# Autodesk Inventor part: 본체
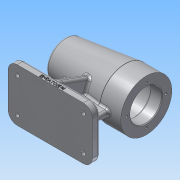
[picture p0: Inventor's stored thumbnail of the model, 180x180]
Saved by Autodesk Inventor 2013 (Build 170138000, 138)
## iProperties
Created: 2018-09
Part Number: 본체
Material: 알루미늄 6061
Document SubType Name: Modeling
Designer: Administrator
Density: 2.71 g/cm^3
Mass: 734.945 g
Surface Area: 663.118 cm^2
Volume: 271.197 cm^3
Author: Administrator
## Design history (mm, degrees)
sketch "스케치1"
  geometry: L1 (53.787, 34)-(25.787, 34); L2 (25.787, 34)-(-54.483, 24.144); L3 (53.787, 0)-(-58.213, 0); L4 (53.787, 34)-(53.787, 21); L5 (53.787, 21)-(38.787, 21); L6 (38.787, 21)-(38.787, 24); L7 (38.787, 24)-(-15.213, 24); L8 (-15.213, 24)-(-15.213, 21); L9 (-15.213, 21)-(-27.213, 21); L10 (-27.213, 21)-(-27.213, 17.5); L11 (-27.213, 17.5)-(-45.213, 17.5); L12 (-45.213, 17.5)-(-45.213, 16); L13 (-45.213, 16)-(-49.213, 16); L14 (-49.213, 16)-(-49.213, 10.5); L15 (-49.213, 10.5)-(-52.213, 10.5); L16 (-52.213, 10.5)-(-52.213, 0); A1 r 80 centre (21.787, 0) between (-54.483, 24.144) and (-58.213, 0); 3 further points
  constraints: 32 end point, 9 parallel, 5 perpendicular, 3 point on line, 2 point on circle, 1 centre point, 1 coincident, 1 horizontal, 1 horizontal alignment, 1 midpoint, 1 vertical alignment
  dimensions: "d1" = 68 diameter of L1 L3; "d3" = 7 deg angle of L2 L1; "d4" = 28 distance of L1.start L1.end; "d5" = 42 diameter of L5 L3; "d6" = 48 diameter of L7 L3; "d7" = 42 diameter of L9 L3; "d8" = 35 diameter of L11 L3; "d9" = 32 diameter of L13 L3; "d10" = 21 diameter of L15 L3; "d11" = 15 distance between parallel lines of L6 L4; "d12" = 54 distance between parallel lines of L6 L8; "d13" = 12 distance between parallel lines of L8 L10; "d14" = 18 distance between parallel lines of L12 L10; "d15" = 4 distance between parallel lines of L12 L14; "d16" = 3 distance between parallel lines of L14 L16; "d17" = 80 radius of A1; "d18" = 112 distance from line of L3.end L4; "d19" = 53.78653 distance from line of point (0, 0) L4; "d20" = 32 distance from line of A1.centre L4
revolve "회전1" sketch "스케치1" stored, may be unused: angle "d23" = 90 deg
fillet "모깎기1" dims "d24" = 3
node "작업 평면1"
sketch "스케치2"
  geometry: L1 (-56, -35)-(56, -35); L2 (56, -35)-(56, 35); L3 (56, 35)-(-56, 35); L4 (-56, 35)-(-56, -35); L5 (-56, -35)-(56, 35); L6 (56, -35)-(-56, 35); 1 further point
  constraints: 12 end point, 2 midpoint, 2 parallel, 1 horizontal, 1 perpendicular
  dimensions: "d26" = 112 distance of L3.end L2.end; "d27" = 70 distance of L2.end L1.end
extrude "돌출1" join sketch "스케치2" distance "d28" = 10; taper "d29" = 0 deg
fillet "모깎기2" dims "d30" = 12
sketch "스케치3"
  geometry: L1 (56, -23)-(56, 23) reference; L2 (-44, -35)-(44, -35) reference; L3 (-56, 23)-(-56, -23) reference; L4 (44, 35)-(-44, 35) reference; A1 r 12 centre (-44, 23) between (-44, 35) and (-56, 23) reference; A2 r 12 centre (-44, -23) between (-56, -23) and (-44, -35) reference; A3 r 12 centre (44, -23) between (44, -35) and (56, -23) reference; A4 r 12 centre (44, 23) between (56, 23) and (44, 35) reference; A5 r 12 centre (44, -23) between (44, -35) and (56, -23) reference; A6 r 12 centre (-44, -23) between (-56, -23) and (-44, -35) reference; A7 r 12 centre (-44, 23) between (-44, 35) and (-56, 23) reference; 5 further points
  constraints: 4 coincident
hole "구멍1" sketch "스케치3" at (-44, 23), (-44, -23), (44, -23), (44, 23) diameter "d31" = 5.5; stored, may be unused: countersink angle "d35" = 90 deg, drill point angle "d37" = 118 deg; dims "d32" = 6, "d33" = 9.5, "d34" = 5.4, "d36" = 10
sketch "스케치4"
  geometry: L1 (38, 4)-(-38, 4); L2 (-38, 4)-(-38, -4); L3 (-38, -4)-(38, -4); L4 (38, -4)-(38, 4); L5 (38, 4)-(-38, -4); L6 (-38, 4)-(38, -4); L7 (56, -23)-(56, 23) reference; L8 (-56, 23)-(-56, -23) reference; 1 further point
  constraints: 12 end point, 2 midpoint, 2 parallel, 1 horizontal, 1 perpendicular
  dimensions: "d38" = 8 distance between parallel lines of L3 L1; "d40" = 18 distance between parallel lines of L7 L4; "d78" = 18 distance between parallel lines of L2 L8 (derived)
extrude "돌출2" join sketch "스케치4" stored distance "d41" = 10; taper "d42" = 0 deg
feature "면 기울기1" dims angle "d43" = 15 deg
node "작업 평면2"
fillet "모깎기5" dims "d68" = 3
sketch "스케치5"
  geometry: L1 (-12, 0)-(-12, 7) reference; L2 (-9, 10)-(19, 10) reference; L3 (19, 10)-(19, 43.427) reference; L4 (27, 43.427)-(27, 10) reference; L5 (27, 10)-(55, 10) reference; L6 (58, 7)-(58, 0) reference; L7 (58, 0)-(-12, 0) reference; L8 (2.36, 46.982)-(-11.819, 8.026); C1 r 24 at (23, 74) reference; A1 r 34 centre (23, 74) between (27, 40.236) and (19, 40.236) reference; A2 r 30.834 centre (23, 74) between (27, 43.427) and (19, 43.427) reference; A3 r 3 centre (-9, 7) between (-9, 10) and (-12, 7) reference; A4 r 3 centre (55, 7) between (58, 7) and (55, 10) reference; 1 further point
  constraints: 2 end point, 2 point on circle, 1 tangent
  dimensions: "d69" = 20 deg angle of L8 L1
feature "리브1" sketch "스케치5" dims "d45" = 1, "d46" = 8, "d47" = 0, "d48" = 0, "d49" = 1, "d50" = 1
sketch "스케치6"
  geometry: 2 further points
  constraints: 1 vertical alignment
  dimensions: "d51" = 26 distance of point (0, 0) point (0, 26)
hole "구멍2" sketch "스케치6" at (0, 26) diameter "d52" = 3.242; stored, may be unused: countersink angle "d56" = 90 deg, drill point angle "d58" = 118 deg; dims "d53" = 8, "d54" = 9.5, "d55" = 4.5, "d57" = 11
sketch "스케치7"
  geometry: L1 (100, 0)-(100, 10) reference; L2 (0, 0)-(88, 0) reference; 2 further points
  constraints: 1 other
  dimensions: "d62" = 56 distance from line of L1 point (44, 3); "d63" = 3 distance from line of point (44, 3) L2
feature "엠보싱1" sketch "스케치7" dims "d1" = 68, "d3" = 7 deg, "d4" = 28, "d5" = 42, "d6" = 48, "d7" = 42, "d8" = 35, "d9" = 32, "d10" = 21, "d11" = 15, "d12" = 54, "d13" = 12, "d14" = 18, "d15" = 4, "d16" = 3, "d17" = 80, "d18" = 112, "d19" = 53.78653, "d20" = 32, "d64" = 0.5, "d65" = 0
fillet "모깎기3" dims "d66" = 3
fillet "모깎기6" dims "d70" = 3
fillet "모깎기7" dims "d71" = 3
fillet "모깎기8" dims "d72" = 3
fillet "모깎기9" dims "d73" = 3, "d74" = 0.3
chamfer "모따기1" distance "d75" = 1; stored, may be unused: second distance "d76" = 2, angle "d77" = 45 deg
node "솔리드1"
mirror "대칭1"
pattern_circular "원형 패턴1" dims angle "d60" = 360 deg
node "투영된 루프1"
node "절단 모서리 투영1"
other parameters: "d25" = -74
